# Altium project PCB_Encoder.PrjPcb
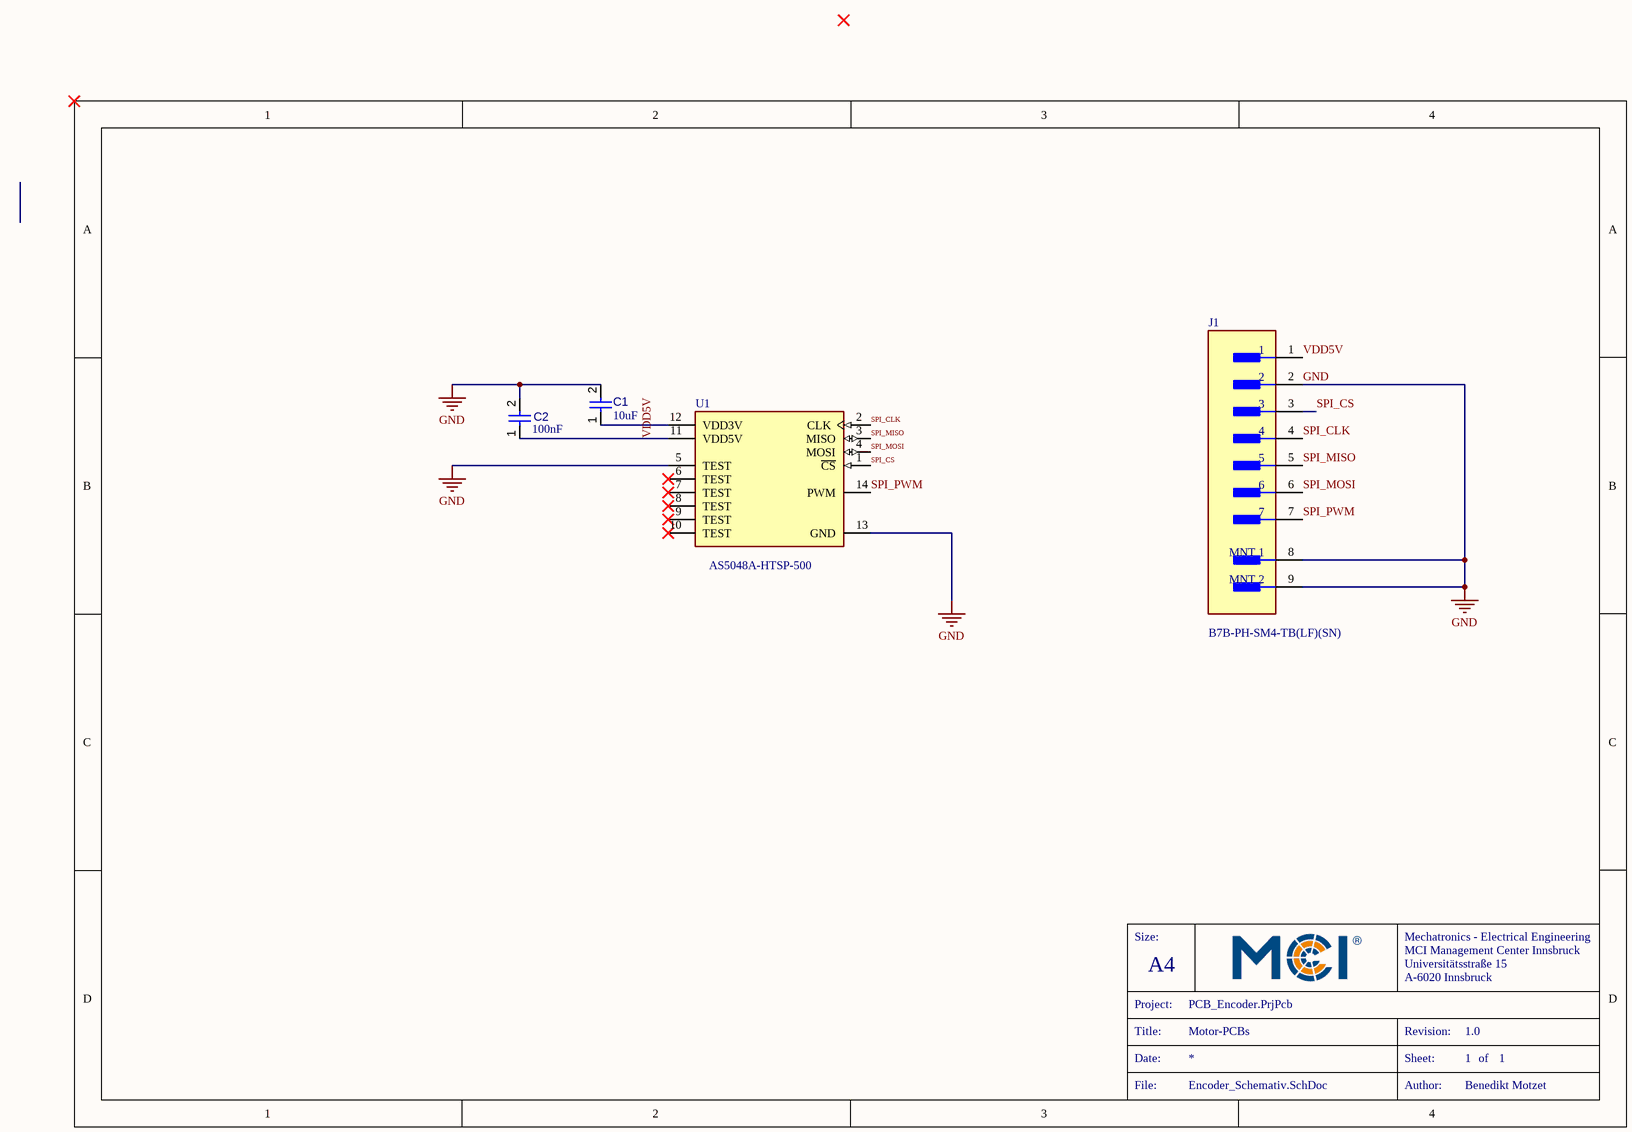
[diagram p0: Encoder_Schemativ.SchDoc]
1 sheet, 4 parts. Net scope: global (net labels, ports and power ports of the same name join across sheets).
Board file: PCBHallsensorFinal1.PcbDoc

## Sheet Encoder_Schemativ.SchDoc: Motor-PCBs
size A4; Author: Benedikt Motzet; CompanyName: MCI Management Center Innsbruck; DrawnBy: Benedikt Motzet; Engineer: Benedikt Motzet; Organization: MCI; Address1: Universitätsstraße 15; Address2: A-6020 Innsbruck; DocumentNumber: 1; Revision: 1.0; SheetNumber: 1; SheetTotal: 1

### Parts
C1  value 10uF  [CAPC0402(1005)60_L]  (hidden comment: Capacitor 470nF +/-40% 10V 0402)
C2  value 100nF  [CAPC1608X90X40NL10T20]  (hidden comment: Capacitor 100 nF +/-10% 50 V 0603)
J1  B7B-PH-SM4-TB(LF)(SN)  [FP-B7B-PH-SM4-TB_LF_SN-MFG]
U1  AS5048A-HTSP-500  [FP-AS5048A-HTSP-500-IPC_C]

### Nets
GND: C1.2 C2.2 J1.2 J1.8(MNT_1) J1.9(MNT_2) U1.5(TEST) U1.13(GND)
SPI_CLK: J1.4 U1.2(CLK)
SPI_CS: J1.3 U1.1(~{CS})
SPI_MISO: J1.5 U1.3(MISO)
SPI_MOSI: J1.6 U1.4(MOSI)
SPI_PWM: J1.7 U1.14(PWM)
VDD5V: C2.1 J1.1 U1.11(VDD5V)
NetC1_1: C1.1 U1.12(VDD3V)

Not connected (* = marked no-connect by the designer): U1 6(TEST)* 7(TEST)* 8(TEST)* 9(TEST)* 10(TEST)*

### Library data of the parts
C1 = CMP-001-00060-4: Chip Capacitor, 470nF +/-40%, 10V, 0402, Thickness 0.6 mm; Tolerance: 20%
C2 = CMP-001-00017-6: Chip Capacitor, 100 nF, +/- 10%, 50 V, 0603 (1608 Metric); Voltage Rating: 50V; Capacitor Type: Ceramic
J1 = CMP-17439-000233-1: CONN HEADER SMD 7POS 2MM; Mated Stacking Heights: 8.6mm; Number of Poles: 7; Voltage Rating (AC): 100V; Contact Resistance: 20mR; Gender: Male; Current Rating: 2A; Insulation Resistance: 1GR
U1 = CMP-22826-000004-1: SENSOR ANGLE 360DEG SMD; Operating Supply Current: 15mA; Min Supply Voltage: 4.5V; Max Supply Voltage: 5.5V; Resolution: 14b; Sensing Method: Hall Effect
